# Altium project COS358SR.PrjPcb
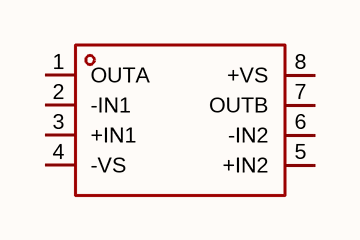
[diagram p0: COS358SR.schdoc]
1 sheet, 1 parts. Net scope: global (net labels, ports and power ports of the same name join across sheets).

## Sheet COS358SR.schdoc
size 127 x 101 mm

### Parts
U?  cos358sr  [SOIC-8_L5.0-W4.0-P1.27-LS6.0-BL]  (value not drawn)

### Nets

Not connected (* = marked no-connect by the designer): U? 1(OUTA) 2(-IN1) 3(+IN1) 4(-VS) 5(+IN2) 6(-IN2) 7(OUTB) 8(+VS)

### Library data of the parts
U? = cos358sr: 放大器数:2;轨到轨:轨到轨输出;增益带宽积(GBW):1.5MHz;输入失调电压(Vos):1mV;压摆率(SR):1V/us;输入偏置电流(Ib):2.5pA;; Manufacturer: COSINE(科山芯创); AddInBom: yes; ModelId: a0552642c23948a584f046f4d7c959d4; ModelTransform: 192.913,236.22,0,0,0,0,0,0,0; Number of Channels: 2; Rail to Rail: 轨到轨输出; Gain Bandwidth Product: 1.5MHz; Vos - Input Offset Voltage: 1mV; Input Offset Voltage Drift(Vos TC): 5uV/℃; Slew Rate: 1V/us; Ib - Input Bias Current: 2.5pA; Input Voltage Noise Density: 28nV/√Hz@1kHz; Common Mode Rejection Ratio(CMRR): 125dB; Quiescent Current: 85uA; Output Current: 45mA; Single supply: 2.1V~5.5V; Dual Supply: 1.05V~2.75V；-2.75V~-1.05V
